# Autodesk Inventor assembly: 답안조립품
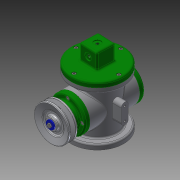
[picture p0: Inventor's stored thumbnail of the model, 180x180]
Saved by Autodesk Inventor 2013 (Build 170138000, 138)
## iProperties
Created: 2018-02
Part Number: 답안조립품
Document SubType Name: Assembly
Designer: Administrator
Author: Administrator
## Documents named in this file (18)
- C:\Users\Administrator\Desktop\480208v1003\답안조립품.iam
- C:\Users\Administrator\Desktop\480208v1003\본체.ipt
- C:\Users\Administrator\Desktop\480208v1003\480208v1003\E-링.ipt
- C:\Users\Administrator\Desktop\480208v1003\480208v1003\V-벨트풀리.ipt
- C:\Users\Administrator\Desktop\480208v1003\480208v1003\덮개.ipt
- C:\Users\Administrator\Desktop\480208v1003\480208v1003\뒤커버.ipt
- C:\Users\Administrator\Desktop\480208v1003\480208v1003\링크.ipt
- C:\Users\Administrator\Desktop\480208v1003\480208v1003\베어링 17 x 40 x 12.ipt
- C:\Users\Administrator\Desktop\480208v1003\480208v1003\볼트 M4 x 8.ipt
- C:\Users\Administrator\Desktop\480208v1003\480208v1003\볼트 M4 x 10.ipt
- C:\Users\Administrator\Desktop\480208v1003\480208v1003\슬라이더.ipt
- C:\Users\Administrator\Desktop\480208v1003\480208v1003\앞커버.ipt
- C:\Users\Administrator\Desktop\480208v1003\480208v1003\오일 실 17 30 8.ipt
- C:\Users\Administrator\Desktop\480208v1003\480208v1003\와셔 4x16.ipt
- C:\Users\Administrator\Desktop\480208v1003\480208v1003\클레비스 핀 6 x 22.ipt
- 클레비스 핀 6 x 22.ipt
- C:\Users\Administrator\Desktop\480208v1003\480208v1003\키 4 x 4 x 12.ipt
- C:\Users\Administrator\Desktop\480208v1003\480208v1003\편심축.ipt
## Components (2 placed, 2 different names)
1. E-링:1
2. V-벨트풀리:1
